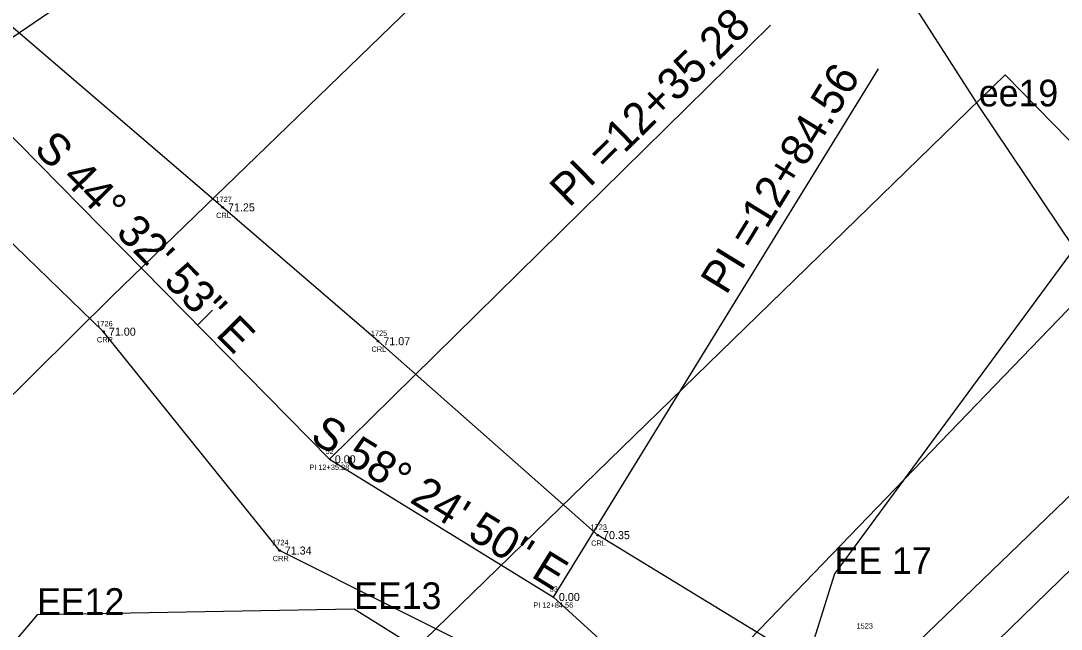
# Model space of a CAD drawing. Extents: x 2500794 to 2511032, y 910653 to 917533.
# Drawn here: x 2505136.3 to 2505331.2, y 913007.8 to 913121.8 of the extents above; entities that cross this region are included whole.
import ezdxf

# ---------------------------------------------------------------- set-up
doc = ezdxf.new("R2010")
doc.units = 0
for name, color, linetype in [('Default', 7, 'Continuous'), ('RD_EX_H2O_txCode', 7, 'Continuous'), ('RD_EX_H2O_WetLd', 7, 'Continuous'), ('RD_EX_Road', 7, 'Continuous'), ('RD_EX_RW', 7, 'Continuous'), ('RD_EX_TX_H2O_ELEV', 7, 'Continuous'), ('RD_EX_UT_txCode', 7, 'Continuous'), ('RD_EX_VEG', 7, 'Continuous'), ('RD_HC_Cl', 7, 'Continuous'), ('RD_HC_Data', 7, 'Continuous'), ('RD_HC_Data_Tic', 7, 'Continuous'), ('RD_HC_Survey_ELEV', 7, 'Continuous'), ('RD_HC_txCode', 7, 'Continuous'), ('RD_SMD_Locator', 7, 'Continuous')]:
    doc.layers.add(name, color=color, linetype=linetype)

# ---------------------------------------------------------------- blocks, each defined once
blk = doc.blocks.new('POINT_DISPLAY')
at = {"layer": 'Default'}
blk.add_line((0, 0), (0, 0), dxfattribs=at)
blk = doc.blocks.new('Wetlands')
at = {"layer": 'Default'}
blk.add_lwpolyline([(636342.944, 231940.182), (636350.209, 231928.858), (636354.738, 231922.099), (636343.337, 231906.608), (636341.382, 231900.373), (636336.102, 231894.003), (636332.117, 231897.645), (636320.479, 231904.936), (636305.393, 231904.66), (636298.923, 231897.016), (636294.296, 231884.265), (636283.587, 231877.605), (636286.971, 231867.991), (636291.686, 231861.221), (636288.9, 231854.468), (636279.39, 231852.849), (636269.749, 231853.613), (636263.179, 231852.028), (636258.651, 231849.987), (636250.174, 231852.919), (636244.941, 231856.37), (636269.687, 231880.898), (636308.974, 231919.839), (636399.189, 232007.15)], dxfattribs=at)

msp = doc.modelspace()

# ---------------------------------------------------------------- linework, layer by layer
at = {"layer": 'RD_EX_H2O_txCode'}
for points in [[(2505244.66, 912978.18), (2505228.35, 913000.65), (2505184.75, 913022.53), (2505151.8, 913063.53), (2505112.58, 913101.46), (2505066, 913175.02), (2505056.4, 913208.97), (2505062.51, 913229.15), (2505037.95, 913240.94)], [(2505281.76, 913002.61), (2505244.38, 913025.41), (2505203.22, 913061.75), (2505174.11, 913086.82), (2505132.24, 913122.64), (2505091.24, 913184.3), (2505079.55, 913206.6), (2505087.26, 913223.44), (2505124.53, 913212.76)]]:
    msp.add_lwpolyline(points, dxfattribs=at)
at = {"layer": 'RD_EX_Road'}
msp.add_lwpolyline([(2505356.25, 913055.37), (2505297.36, 912998.59), (2505254.44, 912956.44), (2505177.06, 912881.21), (2505102.21, 912808.73), (2505026.72, 912735.2), (2504956.07, 912666.21), (2504882.83, 912595.14), (2504825.46, 912547.52), (2504807.83, 912522.24), (2504732.55, 912448.69), (2504654.06, 912372.59), (2504585.1, 912305.45), (2504533.51, 912254.98)], dxfattribs=at)
at = {"layer": 'RD_EX_RW'}
for p in [(2505177.37, 912972.22), (2505350.02, 913081.57)]:
    msp.add_line(p, (2505320.74, 913111.67), dxfattribs=at)
at = {"layer": 'RD_EX_VEG'}
msp.add_lwpolyline([(2505339.13, 913074.53), (2505242.44, 912974.3), (2505088.02, 912824.67), (2504935.82, 912672.7), (2504815.59, 912550.95), (2504817.4, 912591.81)], dxfattribs=at)
at = {"layer": 'RD_HC_Cl'}
for p, q in [((2504540.35, 912247.97), (2505598.79, 913277.5)), ((2505123.69, 913111.17), (2505194.12, 913039.62)), ((2505194.12, 913039.62), (2505236.1, 913013.81)), ((2505236.1, 913013.81), (2505353.01, 912906.84))]:
    msp.add_line(p, q, dxfattribs=at)
at = {"layer": 'RD_HC_Data'}
for p, q in [((2505123.69, 913111.17), (2505219.44, 913176.56)), ((2505194.12, 913039.62), (2505276.75, 913120.96)), ((2505236.1, 913013.81), (2505296.96, 913112.79))]:
    msp.add_line(p, q, dxfattribs=at)
at = {"layer": 'RD_HC_Data_Tic'}
msp.add_line((2505169.37, 913064.76), (2505172.22, 913067.57), dxfattribs=at)
at = {"layer": 'RD_SMD_Locator'}
for centre in [(2505174.11, 913086.82), (2505151.8, 913063.53), (2505203.22, 913061.75), (2505244.38, 913025.41), (2505184.75, 913022.53)]:
    msp.add_circle(centre, 0.15, dxfattribs=at)

# ---------------------------------------------------------------- block references
at = {"layer": 'Default', "xscale": 3.937007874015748, "yscale": 3.937007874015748}
for name, p in [('Wetlands', (0, 0)), ('POINT_DISPLAY', (2505315.78, 913105.74)), ('POINT_DISPLAY', (2505315.78, 913105.74)), ('POINT_DISPLAY', (2505288.73, 913018.14)), ('POINT_DISPLAY', (2505288.73, 913018.14)), ('POINT_DISPLAY', (2505198.74, 913011.56)), ('POINT_DISPLAY', (2505198.74, 913011.56)), ('POINT_DISPLAY', (2505139.34, 913010.47)), ('POINT_DISPLAY', (2505139.34, 913010.47))]:
    msp.add_blockref(name, p, dxfattribs=at)
at = {"layer": 'RD_EX_H2O_WetLd', "xscale": 3.937007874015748, "yscale": 3.937007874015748}
msp.add_blockref('Wetlands', (0, 0), dxfattribs=at)

# ---------------------------------------------------------------- texts
at = {"layer": 'Default'}
for s, p in [('ee19', (2505315.78, 913105.74)), ('ee19', (2505315.78, 913105.74)), ('EE 17', (2505288.73, 913018.14)), ('EE 17', (2505288.73, 913018.14)), ('EE12', (2505139.34, 913010.47)), ('EE12', (2505139.34, 913010.47)), ('EE13', (2505198.74, 913011.56)), ('EE13', (2505198.74, 913011.56))]:
    msp.add_text(s, height=5, dxfattribs=at).set_placement(p)
at = {"layer": 'RD_EX_H2O_txCode'}
for s, p in [('1727', (2505172.76, 913087.82)), ('CRL', (2505172.88, 913084.82)), ('1726', (2505150.43, 913064.53)), ('CRR', (2505150.55, 913061.53)), ('1725', (2505201.87, 913062.75)), ('CRL', (2505201.99, 913059.75)), ('1723', (2505243.03, 913026.41)), ('1724', (2505183.4, 913023.53)), ('CRL', (2505243.15, 913023.41)), ('CRR', (2505183.5, 913020.53))]:
    msp.add_text(s, height=1, dxfattribs=at).set_placement(p)
at = {"layer": 'RD_EX_TX_H2O_ELEV'}
for s, p in [('71.25', (2505175.11, 913086.07)), ('71.00', (2505152.8, 913062.78)), ('71.07', (2505204.22, 913061)), ('70.35', (2505245.38, 913024.66)), ('71.34', (2505185.75, 913021.78))]:
    msp.add_text(s, height=1.5, dxfattribs=at).set_placement(p)
at = {"layer": 'RD_EX_UT_txCode'}
msp.add_text('1523', height=1, dxfattribs=at).set_placement((2505292.86, 913007.91))
at = {"layer": 'RD_HC_Data'}
for s, rotation, p in [('PI =12+35.28', 44.5479, (2505239.04, 913086.64)), ('PI =12+84.56', 58.4139, (2505268.44, 913070.23)), ('S 44%%d 32\' 53" E', 314.5479, (2505138.52, 913097.53)), ('S 58%%d 24\' 50" E', 328.4139, (2505190.26, 913043.17))]:
    msp.add_text(s, height=6, rotation=rotation, dxfattribs=at).set_placement(p)
at = {"layer": 'RD_HC_Survey_ELEV'}
for p in [(2505195.12, 913038.87), (2505237.1, 913013.06)]:
    msp.add_text('0.00', height=1.5, dxfattribs=at).set_placement(p)
at = {"layer": 'RD_HC_txCode'}
for s, p in [('52', (2505193.39, 913040.62)), ('PI 12+35.28', (2505190.34, 913037.62)), ('53', (2505235.37, 913014.81)), ('PI 12+84.56', (2505232.3, 913011.81))]:
    msp.add_text(s, height=1, dxfattribs=at).set_placement(p)

doc.saveas('drawing.dxf')
